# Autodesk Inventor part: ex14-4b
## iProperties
Author: J. DESIGNER
Created: 2001-10
Part Number: ex14-4b
Document SubType Name: Modeling
Designer: J. DESIGNER
Control State: 0
Master: False
Checked Out: False
PropertySet Name: Design Tracking Control
Shininess: 64.0
Angle Display Precision: 2
Document Length Units: 11272
Document Angle Units: 11286
Document Time Units: 11279
Document Mass Units: 11290
Document Length Units Precision: 3
Document Angle Units Precision: 2
Compacted: False
PropertySet Name: _Private Model Information
Density: 0.0
Volumn: 0.0
Area: 0.0
PropertySet Name: Model Information
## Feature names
1. Extrusion1
2. Hole1
3. Hole2
